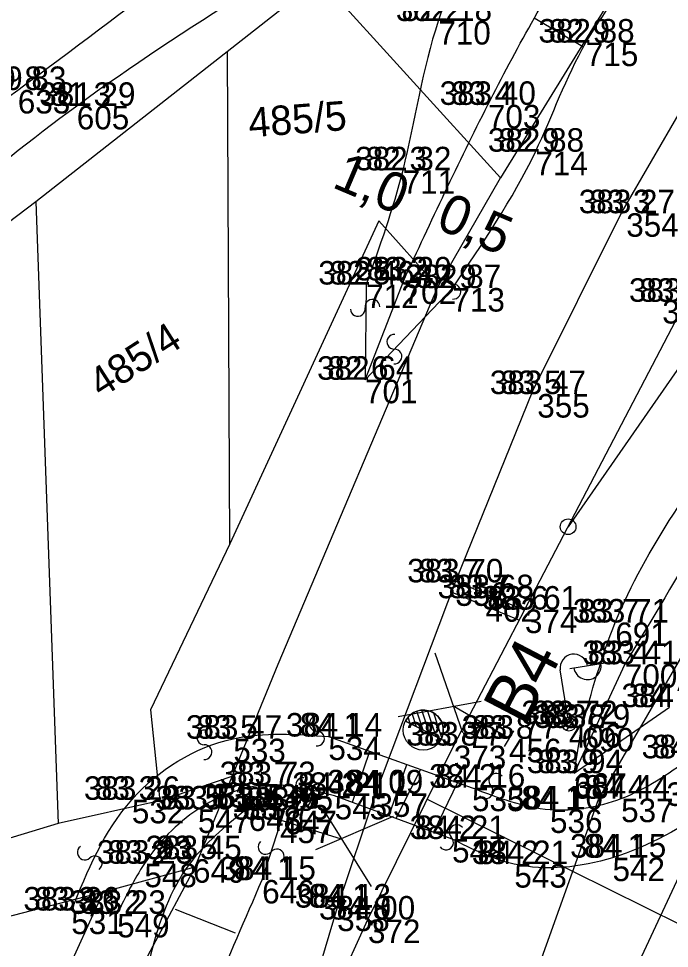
# Model space of a CAD drawing. Extents: x -514509 to -512782, y -1144610 to -1143439.
# Drawn here: x -513724.22 to -513691.01, y -1143978.71 to -1143931.26 of the extents above; entities that cross this region are included whole.
import ezdxf

# ---------------------------------------------------------------- set-up
doc = ezdxf.new("R2010")
doc.units = 0
for name, color, linetype in [('Vrstva 10', 7, 'Continuous'), ('Vrstva 11', 7, 'Continuous'), ('Vrstva 14', 7, 'Continuous'), ('Vrstva 15', 7, 'Continuous'), ('Vrstva 18', 7, 'Continuous'), ('Vrstva 30', 7, 'Continuous'), ('Vrstva 57', 7, 'Continuous'), ('Vrstva 58', 7, 'Continuous'), ('Vrstva 59', 7, 'Continuous'), ('Vrstva 6', 7, 'Continuous'), ('Vrstva 60', 7, 'Continuous'), ('Vrstva 8', 7, 'Continuous'), ('Vrstva 9', 7, 'Continuous')]:
    doc.layers.add(name, color=color, linetype=linetype)

msp = doc.modelspace()

# ---------------------------------------------------------------- linework, layer by layer
at = {"layer": 'Vrstva 10'}
msp.add_line((-513700.389, -1143960.838), (-513700.389, -1143960.838), dxfattribs=at)
for points in [[(-513668.231, -1143896.863), (-513674.194, -1143899.653), (-513689.332, -1143922.659), (-513699.619, -1143939.375), (-513708.846, -1143929.228), (-513723.333, -1143940.602), (-513785.775, -1143987.984), (-513791.13, -1143992.447), (-513811.589, -1144005.852)], [(-513669.195, -1143897.314), (-513674.194, -1143899.653), (-513689.332, -1143922.659), (-513699.619, -1143939.375), (-513708.846, -1143929.228), (-513723.333, -1143940.602), (-513785.775, -1143987.984), (-513791.13, -1143992.447), (-513811.589, -1144005.852)], [(-513697.911, -1143931.214), (-513695.387, -1143932.694)], [(-513706.539, -1143949.687), (-513704.567, -1143944.623)], [(-513706.481, -1143944.833), (-513706.539, -1143949.687), (-513702.078, -1143945.01)], [(-513701.904, -1143959.967), (-513698.396, -1143961.443)], [(-513702.116, -1143960.528), (-513698.662, -1143961.967)], [(-513693.278, -1143964.208), (-513695.862, -1143969.773)], [(-513695.862, -1143969.773), (-513691.007, -1143966.405)], [(-513695.862, -1143969.773), (-513695.487, -1143967.462)], [(-513708.406, -1143967.904), (-513701.08, -1143970.51)], [(-513702.098, -1143973.134), (-513708.093, -1143970.93)], [(-513711.792, -1143975.221), (-513710.651, -1143971.693), (-513712.482, -1143971.524)], [(-513713.147, -1143977.932), (-513716.205, -1143976.72)]]:
    msp.add_lwpolyline(points, dxfattribs=at)
msp.add_lwpolyline([(-513714.127, -1144025.605), (-513694.625, -1143971.12), (-513684.432, -1143953.63), (-513674.387, -1143945.337), (-513683.744, -1143960.501)], close=True, dxfattribs=at)
msp.add_lwpolyline([(-513714.127, -1144025.605), (-513694.625, -1143971.12), (-513684.432, -1143953.63), (-513674.387, -1143945.337), (-513683.744, -1143960.501)], close=True, dxfattribs=at)
for points in [[(-513674.274, -1143843.477), (-513674.46, -1143843.597), (-513687.396, -1143852.464), (-513702.821, -1143867.073), (-513717.154, -1143882.054), (-513727.841, -1143898.171), (-513737.859, -1143911.275), (-513753.355, -1143924.614), (-513772.465, -1143940.017), (-513793.162, -1143954.594), (-513811.59, -1143964.008), (-513831.445, -1143975.36)], [(-513808.418, -1143998.941), (-513792.063, -1143986.974), (-513776.16, -1143976.17), (-513764.915, -1143968.271), (-513753.689, -1143959.442), (-513740.521, -1143947.369), (-513724.263, -1143934.903), (-513707.902, -1143922.425), (-513689.125, -1143907.833), (-513675.979, -1143896.958), (-513671.6, -1143893.116), (-513670.058, -1143892.633), (-513668.651, -1143892.952)], [(-513683.099, -1143898.637), (-513699.256, -1143911.331), (-513710.594, -1143919.479), (-513728.885, -1143933.244)], [(-513754.963, -1143964.828), (-513734.448, -1143946.693), (-513721.252, -1143935.706), (-513704.018, -1143924.219), (-513687.594, -1143911.382), (-513671.785, -1143899.771)], [(-513683.213, -1143910.938), (-513687.044, -1143912.015), (-513695.556, -1143919.646), (-513702.805, -1143931.383), (-513704.619, -1143939.004), (-513706.481, -1143944.833)], [(-513702.078, -1143945.01), (-513697.846, -1143938.052), (-513695.267, -1143932.477), (-513689.169, -1143924.31), (-513684.661, -1143916.778), (-513682.277, -1143912.267), (-513683.213, -1143910.938)], [(-513695.487, -1143967.462), (-513693.771, -1143962.082), (-513687.144, -1143951.344), (-513675.991, -1143935.639), (-513665.851, -1143921.979), (-513659.109, -1143913.393)], [(-513704.567, -1143944.623), (-513700.272, -1143935.661), (-513695.642, -1143927.4), (-513688.541, -1143916.99)], [(-513676.992, -1143939.46), (-513684.964, -1143950.778), (-513693.278, -1143964.208)], [(-513701.08, -1143970.51), (-513697.096, -1143971.623), (-513693.468, -1143971.065), (-513689.984, -1143969.011), (-513686.173, -1143966.028)], [(-513721.529, -1143976.776), (-513718.443, -1143971.126), (-513713.265, -1143968.009), (-513708.406, -1143967.904)], [(-513684.324, -1143968.239), (-513688.735, -1143971.438), (-513693.906, -1143974.084), (-513698.921, -1143974.409), (-513702.098, -1143973.134)], [(-513708.093, -1143970.93), (-513711.544, -1143970.375), (-513715.07, -1143971.617), (-513717.799, -1143974.386), (-513719.187, -1143976.951)], [(-513712.482, -1143971.524), (-513715.316, -1143974.16), (-513718.447, -1143983.854), (-513727.631, -1144009.259), (-513733.222, -1144035.94), (-513739.194, -1144065.123), (-513743.945, -1144087.628), (-513746.069, -1144099.575)], [(-513738.186, -1144099.438), (-513735.334, -1144077.739), (-513732.007, -1144054.345), (-513728.401, -1144031.675), (-513722.813, -1144007.123), (-513716.72, -1143987.115), (-513711.792, -1143975.221)]]:
    msp.add_spline(points, degree=3, dxfattribs=at)
at = {"layer": 'Vrstva 14'}
for points in [[(-513706.311, -1143968.66), (-513707.201, -1143971.258)], [(-513704.42, -1143969.337), (-513705.328, -1143971.934)], [(-513703.713, -1143969.587), (-513704.968, -1143972.083)], [(-513701.82, -1143970.249), (-513703.053, -1143972.775)]]:
    msp.add_lwpolyline(points, dxfattribs=at)
at = {"layer": 'Vrstva 15'}
msp.add_lwpolyline([(-513703.367, -1143971.104), (-513649.603, -1143997.738)], dxfattribs=at)
at = {"layer": 'Vrstva 18'}
for centre, radius, start, end in [((-513702.047, -1143944.441), 0.376, 84.3625, 270.6736), ((-513702.034, -1143945.194), 0.377, 263.6864, 91.3496), ((-513706.164, -1143945.967), 0.377, 1.1152, 188.7784), ((-513706.909, -1143946.077), 0.376, 181.7912, 8.1024), ((-513705.048, -1143947.751), 0.376, 84.3625, 270.6736), ((-513705.035, -1143948.504), 0.377, 263.6864, 91.3496), ((-513709.005, -1143967.245), 0.376, 84.3625, 270.6736), ((-513714.746, -1143967.942), 0.376, 84.3625, 270.6736), ((-513708.992, -1143967.998), 0.377, 263.6864, 91.3496), ((-513714.733, -1143968.695), 0.377, 263.6864, 91.3496), ((-513699.843, -1143970.161), 0.376, 37.979, 224.2902), ((-513709.701, -1143970.379), 0.376, 84.3625, 270.6736), ((-513709.688, -1143971.132), 0.377, 263.6864, 91.3496), ((-513700.379, -1143970.69), 0.377, 217.303, 44.9662), ((-513701.871, -1143972.779), 0.376, 37.721, 224.0322), ((-513702.409, -1143973.306), 0.377, 217.045, 44.7082), ((-513720.843, -1143973.818), 0.376, 126.1513, 312.4624), ((-513711.619, -1143973.535), 0.376, 133.4198, 319.731), ((-513711.042, -1143974.019), 0.377, 312.7438, 140.407), ((-513720.331, -1143974.371), 0.377, 305.4752, 133.1385)]:
    msp.add_arc(centre, radius, start, end, dxfattribs=at)
at = {"layer": 'Vrstva 30'}
for p, q in [((-513701.552, -1143967.709), (-513702.968, -1143963.646)), ((-513704.845, -1143966.873), (-513700.613, -1143966.095)), ((-513699.188, -1143968.006), (-513702.011, -1143966.363)), ((-513699.421, -1143968.409), (-513698.953, -1143967.602)), ((-513710.741, -1143971.696), (-513711.02, -1143972.588)), ((-513710.881, -1143972.143), (-513707.761, -1143973.114)), ((-513705.111, -1143971.983), (-513709.064, -1143973.686)), ((-513708.509, -1143971.903), (-513706.222, -1143975.549))]:
    msp.add_line(p, q, dxfattribs=at)
at = {"layer": 'Vrstva 6'}
for p, q in [((-513696.091, -1143964.426), (-513694.293, -1143964.142)), ((-513696.191, -1143966.923), (-513696.575, -1143964.503)), ((-513696.451, -1143967.422), (-513696.089, -1143966.924)), ((-513696.254, -1143967.597), (-513695.86, -1143967.055))]:
    msp.add_line(p, q, dxfattribs=at)
for points in [[(-513711.674, -1143988.808), (-513706.391, -1143977.238), (-513702.009, -1143968.362), (-513698.385, -1143961.423), (-513690.28, -1143945.92), (-513684.59, -1143935.49), (-513679.681, -1143927.309), (-513672.807, -1143917.428), (-513665.353, -1143907.777), (-513658.001, -1143899.181), (-513648.869, -1143889.527), (-513638.707, -1143879.951), (-513628.616, -1143872.033), (-513618.02, -1143863.718), (-513607.812, -1143855.708), (-513601.226, -1143850.54)], [(-513618.287, -1143857.461), (-513629.826, -1143866.459), (-513640.68, -1143874.922), (-513651.12, -1143884.499), (-513660.485, -1143894.222), (-513665.52, -1143899.973), (-513673.196, -1143909.558), (-513682, -1143921.71), (-513688.486, -1143932.573), (-513693.41, -1143941.08), (-513697.99, -1143950.27), (-513701.934, -1143960.028), (-513706.014, -1143970.804), (-513707.963, -1143976.628), (-513710.975, -1143986.754), (-513715.38, -1144000.83), (-513719.14, -1144013.09)], [(-513659.798, -1143909.039), (-513667.128, -1143918.358), (-513674.858, -1143928.206), (-513681.812, -1143937.007), (-513686.931, -1143944.023), (-513688.954, -1143946.817), (-513696.173, -1143957.193)]]:
    msp.add_lwpolyline(points, dxfattribs=at)
msp.add_circle((-513696.137, -1143967.269), 0.35, dxfattribs=at)
msp.add_circle((-513696.137, -1143967.269), 0.35, dxfattribs=at)
for centre, start, end in [((-513695.883, -1143964.393), 9, 189), ((-513695.19, -1143964.292), 188.2974, 9.7026)]:
    msp.add_arc(centre, 0.7, start, end, dxfattribs=at)
at = {"layer": 'Vrstva 60'}
for p, q in [((-513702.8, -1143931.38), (-513702.8, -1143931.38)), ((-513695.27, -1143932.48), (-513695.27, -1143932.48)), ((-513721.25, -1143935.71), (-513721.25, -1143935.71)), ((-513700.27, -1143935.66), (-513700.27, -1143935.66)), ((-513697.85, -1143938.05), (-513697.85, -1143938.05)), ((-513704.62, -1143939), (-513704.62, -1143939)), ((-513693.21, -1143941.19), (-513693.21, -1143941.19)), ((-513704.57, -1143944.62), (-513704.57, -1143944.62)), ((-513706.48, -1143944.83), (-513706.48, -1143944.83)), ((-513702.08, -1143945.01), (-513702.08, -1143945.01)), ((-513706.54, -1143949.69), (-513706.54, -1143949.69)), ((-513697.75, -1143950.42), (-513697.75, -1143950.42)), ((-513701.93, -1143960.03), (-513701.93, -1143960.03)), ((-513700.39, -1143960.84), (-513700.39, -1143960.84)), ((-513698.38, -1143961.42), (-513698.38, -1143961.42)), ((-513693.77, -1143962.08), (-513693.77, -1143962.08)), ((-513693.28, -1143964.21), (-513693.28, -1143964.21)), ((-513691.01, -1143966.4), (-513691.01, -1143966.4)), ((-513696.14, -1143967.27), (-513696.14, -1143967.27)), ((-513695.49, -1143967.46), (-513695.49, -1143967.46)), ((-513713.26, -1143968.01), (-513713.26, -1143968.01)), ((-513708.41, -1143967.9), (-513708.41, -1143967.9)), ((-513699.19, -1143968.01), (-513699.19, -1143968.01)), ((-513702.01, -1143968.36), (-513702.01, -1143968.36)), ((-513695.86, -1143969.77), (-513695.86, -1143969.77)), ((-513711.54, -1143970.38), (-513711.54, -1143970.38)), ((-513706.01, -1143970.8), (-513706.01, -1143970.8)), ((-513701.08, -1143970.51), (-513701.08, -1143970.51)), ((-513718.44, -1143971.13), (-513718.44, -1143971.13)), ((-513708.09, -1143970.93), (-513708.09, -1143970.93)), ((-513693.47, -1143971.07), (-513693.47, -1143971.07)), ((-513715.07, -1143971.62), (-513715.07, -1143971.62)), ((-513712.48, -1143971.52), (-513712.48, -1143971.52)), ((-513710.65, -1143971.69), (-513710.65, -1143971.69)), ((-513697.1, -1143971.62), (-513697.1, -1143971.62)), ((-513710.88, -1143972.14), (-513710.88, -1143972.14)), ((-513702.1, -1143973.13), (-513702.1, -1143973.13)), ((-513715.32, -1143974.16), (-513715.32, -1143974.16)), ((-513693.91, -1143974.08), (-513693.91, -1143974.08)), ((-513717.8, -1143974.39), (-513717.8, -1143974.39)), ((-513698.92, -1143974.41), (-513698.92, -1143974.41)), ((-513711.79, -1143975.22), (-513711.79, -1143975.22)), ((-513721.53, -1143976.78), (-513721.53, -1143976.78)), ((-513719.19, -1143976.95), (-513719.19, -1143976.95)), ((-513707.96, -1143976.63), (-513707.96, -1143976.63)), ((-513706.39, -1143977.24), (-513706.39, -1143977.24))]:
    msp.add_line(p, q, dxfattribs=at)
at = {"layer": 'Vrstva 8'}
for p, q in [((-513713.444, -1143958.06), (-513713.559, -1143932.938)), ((-513723.333, -1143940.602), (-513722.204, -1143972.33)), ((-513703.58, -1143967.568), (-513703.895, -1143966.607)), ((-513703.249, -1143967.736), (-513703.636, -1143966.555)), ((-513702.918, -1143967.904), (-513703.353, -1143966.574)), ((-513704.242, -1143967.232), (-513704.346, -1143966.915)), ((-513703.911, -1143967.4), (-513704.132, -1143966.725)), ((-513702.621, -1143967.965), (-513703.035, -1143966.702)), ((-513702.652, -1143968.038), (-513704.48, -1143967.112)), ((-513704.48, -1143967.112), (-513702.652, -1143968.037)), ((-513702.652, -1143968.037), (-513702.652, -1143968.038)), ((-513702.651, -1143968.038), (-513702.009, -1143968.362)), ((-513717.015, -1143971.18), (-513713.314, -1143969.916)), ((-513719.895, -1143975.826), (-513715.208, -1143974.553)), ((-513708.439, -1143976.476), (-513707.486, -1143976.779)), ((-513706.838, -1143977.015), (-513705.943, -1143977.46))]:
    msp.add_line(p, q, dxfattribs=at)
for points in [[(-513715.208, -1143974.553), (-513710.975, -1143964.21), (-513702.825, -1143944.95), (-513699.619, -1143939.375)], [(-513702.825, -1143944.95), (-513705.834, -1143941.573), (-513713.444, -1143958.06), (-513717.489, -1143966.541), (-513717.015, -1143971.18), (-513722.204, -1143972.33), (-513733.916, -1143975.895), (-513785.775, -1143987.984)], [(-513715.208, -1143974.553), (-513721.688, -1143986.691), (-513730.636, -1144020.555), (-513743.109, -1144073.852), (-513744.806, -1144082.081)], [(-513825.323, -1144036.014), (-513781.427, -1144111.593), (-513791.13, -1143992.447), (-513731.905, -1143978.943), (-513719.895, -1143975.826)], [(-513748.803, -1144085.025), (-513745.712, -1144073.233), (-513730.239, -1144005.665), (-513724.769, -1143986.548), (-513719.895, -1143975.826)]]:
    msp.add_lwpolyline(points, dxfattribs=at)
for centre, radius in [((-513696.175, -1143957.193), 0.4), ((-513703.57, -1143967.572), 1.023)]:
    msp.add_circle(centre, radius, dxfattribs=at)
msp.add_arc((-513703.566, -1143967.575), 1.024, 333.1694, 153.1302, dxfattribs=at)

# ---------------------------------------------------------------- texts
at = {"layer": 'Vrstva 11'}
for s, p in [('1,0', (-513708.285, -1143939.842)), ('0,5', (-513703.001, -1143941.924))]:
    msp.add_text(s, height=2, rotation=337.0813, dxfattribs=at).set_placement(p)
at = {"layer": 'Vrstva 57'}
for s, p in [('82 2 ', (-513704.683, -1143931.38)), ('82 9 ', (-513697.158, -1143932.48)), ('79 8 ', (-513726.15, -1143934.9)), ('81 3 ', (-513722.623, -1143935.71)), ('83 4 ', (-513702.153, -1143935.66)), ('82 9 ', (-513699.738, -1143938.05)), ('82 3 ', (-513706.503, -1143939)), ('83 3 ', (-513695.093, -1143941.19)), ('82 5 ', (-513708.363, -1143944.83)), ('83 2 ', (-513706.453, -1143944.62)), ('82 9 ', (-513703.968, -1143945.01)), ('83 2 ', (-513692.533, -1143945.71)), ('82 6 ', (-513708.464, -1143949.69)), ('83 5 ', (-513699.633, -1143950.42)), ('83 7 ', (-513703.813, -1143960.03)), ('83 7 ', (-513702.273, -1143960.84)), ('83 6 ', (-513700.304, -1143961.42)), ('83 7 ', (-513695.653, -1143962.08)), ('83 4 ', (-513695.163, -1143964.21)), ('84 6 ', (-513692.934, -1143966.4)), ('83 7 ', (-513698.023, -1143967.27)), ('83 8 ', (-513697.373, -1143967.46)), ('83 5 ', (-513715.143, -1143968.01)), ('84 1 ', (-513709.868, -1143967.9)), ('83 8 ', (-513701.073, -1143968.01)), ('83 8 ', (-513703.893, -1143968.36)), ('84 7 ', (-513691.863, -1143969.01)), ('83 9 ', (-513697.748, -1143969.77)), ('83 7 ', (-513713.423, -1143970.38)), ('84 2 ', (-513702.963, -1143970.51)), ('83 3 ', (-513720.323, -1143971.13)), ('84 2 ', (-513709.973, -1143970.93)), ('84 1 ', (-513707.468, -1143970.8)), ('84 4 ', (-513695.353, -1143971.07)), ('83 5 ', (-513716.953, -1143971.62)), ('83 5 ', (-513714.363, -1143971.52)), ('84 1 ', (-513698.558, -1143971.62)), ('84 0 ', (-513712.598, -1143971.69)), ('83 7 ', (-513712.763, -1143972.14)), ('84 2 ', (-513703.983, -1143973.13)), ('83 2 ', (-513719.683, -1143974.39)), ('83 5 ', (-513717.203, -1143974.16)), ('84 2 ', (-513700.803, -1143974.41)), ('84 1 ', (-513695.368, -1143974.08)), ('84 1 ', (-513713.248, -1143975.22)), ('83 3 ', (-513723.413, -1143976.78)), ('84 1 ', (-513709.418, -1143976.63)), ('83 2 ', (-513721.073, -1143976.95)), ('84 0 ', (-513708.338, -1143977.24))]:
    msp.add_text(s, height=1.2, dxfattribs=at).set_placement(p)
at = {"layer": 'Vrstva 58'}
for s, p in [('382 18', (-513704.966, -1143931.38)), ('382 88', (-513697.691, -1143932.48)), ('379 83', (-513726.688, -1143934.9)), ('381 29', (-513723.164, -1143935.71)), ('383 40', (-513702.73, -1143935.66)), ('382 88', (-513700.271, -1143938.05)), ('382 32', (-513707.041, -1143939)), ('383 27', (-513695.631, -1143941.19)), ('382 46', (-513708.926, -1143944.83)), ('383 20', (-513707.03, -1143944.62)), ('382 87', (-513704.501, -1143945.01)), ('383 25', (-513693.071, -1143945.71)), ('383 24', (-513691.371, -1143946.82)), ('382 64', (-513708.986, -1143949.69)), ('383 47', (-513700.171, -1143950.42)), ('383 70', (-513704.39, -1143960.03)), ('383 68', (-513702.836, -1143960.84)), ('383 61', (-513700.57, -1143961.42)), ('383 71', (-513695.936, -1143962.08)), ('383 41', (-513695.446, -1143964.21)), ('384 62', (-513693.456, -1143966.4)), ('383 72', (-513698.561, -1143967.27)), ('383 79', (-513697.914, -1143967.46)), ('383 47', (-513715.681, -1143968.01)), ('384 14', (-513710.576, -1143967.9)), ('383 77', (-513701.611, -1143968.01)), ('383 77', (-513704.431, -1143968.36)), ('384 67', (-513692.426, -1143969.01)), ('383 94', (-513698.284, -1143969.77)), ('383 73', (-513713.961, -1143970.38)), ('384 16', (-513703.27, -1143970.51)), ('383 26', (-513720.886, -1143971.13)), ('384 21', (-513710.256, -1143970.93)), ('384 09', (-513708.473, -1143970.8)), ('384 44', (-513695.891, -1143971.07)), ('383 51', (-513717.236, -1143971.62)), ('383 53', (-513714.901, -1143971.52)), ('384 10', (-513699.305, -1143971.62)), ('384 58', (-513691.161, -1143971.44)), ('383 95', (-513713.074, -1143971.69)), ('383 75', (-513713.301, -1143972.14)), ('384 21', (-513704.266, -1143973.13)), ('383 23', (-513720.221, -1143974.39)), ('383 45', (-513717.741, -1143974.16)), ('384 21', (-513701.086, -1143974.41)), ('384 15', (-513696.076, -1143974.08)), ('384 15', (-513713.956, -1143975.22)), ('383 26', (-513723.976, -1143976.78)), ('384 13', (-513710.126, -1143976.63)), ('383 23', (-513721.611, -1143976.95)), ('384 00', (-513708.888, -1143977.24))]:
    msp.add_text(s, height=1.2, dxfattribs=at).set_placement(p)
at = {"layer": 'Vrstva 59'}
for s, p in [('710', (-513702.8, -1143932.58)), ('715', (-513695.27, -1143933.68)), ('633', (-513724.26, -1143936.1)), ('605', (-513721.25, -1143936.91)), ('703', (-513700.27, -1143936.86)), ('714', (-513697.85, -1143939.25)), ('711', (-513704.62, -1143940.2)), ('354', (-513693.21, -1143942.39)), ('702', (-513704.57, -1143945.82)), ('712', (-513706.48, -1143946.03)), ('713', (-513702.08, -1143946.21)), ('701', (-513706.54, -1143950.89)), ('355', (-513697.75, -1143951.62)), ('356', (-513701.93, -1143961.23)), ('402', (-513700.39, -1143962.04)), ('374', (-513698.38, -1143962.62)), ('691', (-513693.77, -1143963.28)), ('700', (-513693.28, -1143965.41)), ('406', (-513696.14, -1143968.47)), ('690', (-513695.49, -1143968.66)), ('533', (-513713.26, -1143969.21)), ('534', (-513708.41, -1143969.1)), ('456', (-513699.19, -1143969.21)), ('373', (-513702.01, -1143969.56)), ('667', (-513695.86, -1143970.97)), ('546', (-513711.54, -1143971.58)), ('357', (-513706.01, -1143972)), ('535', (-513701.08, -1143971.71)), ('532', (-513718.44, -1143972.33)), ('545', (-513708.09, -1143972.13)), ('537', (-513693.47, -1143972.27)), ('547', (-513715.07, -1143972.82)), ('648', (-513712.48, -1143972.72)), ('647', (-513710.65, -1143972.89)), ('536', (-513697.1, -1143972.82)), ('457', (-513710.88, -1143973.34)), ('544', (-513702.1, -1143974.33)), ('649', (-513715.32, -1143975.36)), ('542', (-513693.91, -1143975.28)), ('548', (-513717.8, -1143975.59)), ('543', (-513698.92, -1143975.61)), ('646', (-513711.79, -1143976.42)), ('531', (-513721.53, -1143977.98)), ('549', (-513719.19, -1143978.15)), ('358', (-513707.96, -1143977.83)), ('372', (-513706.39, -1143978.44))]:
    msp.add_text(s, height=1.2, dxfattribs=at).set_placement(p)
at = {"layer": 'Vrstva 9'}
for s, height, rotation, p in [('485/5', 1.5, 4.3601, (-513712.437, -1143937.319)), ('485/4', 1.5, 32.6485, (-513720.009, -1143950.65)), ('B4', 2.5, 62.4232, (-513698.387, -1143967.442))]:
    msp.add_text(s, height=height, rotation=rotation, dxfattribs=at).set_placement(p)

doc.saveas('drawing.dxf')
